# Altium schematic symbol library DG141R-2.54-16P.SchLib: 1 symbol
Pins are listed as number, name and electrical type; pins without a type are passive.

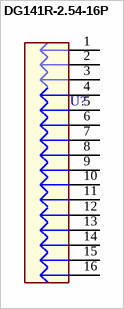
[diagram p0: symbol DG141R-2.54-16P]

## DG141R-2.54-16P
designator U?  (value not drawn)
DG129-5.0-03P-14-00AH
footprint DG141R-2.54-16P
pins: 1, 2, 3, 4, 5, 6, 7, 8, 9, 10, 11, 12, 13, 14, 15, 16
